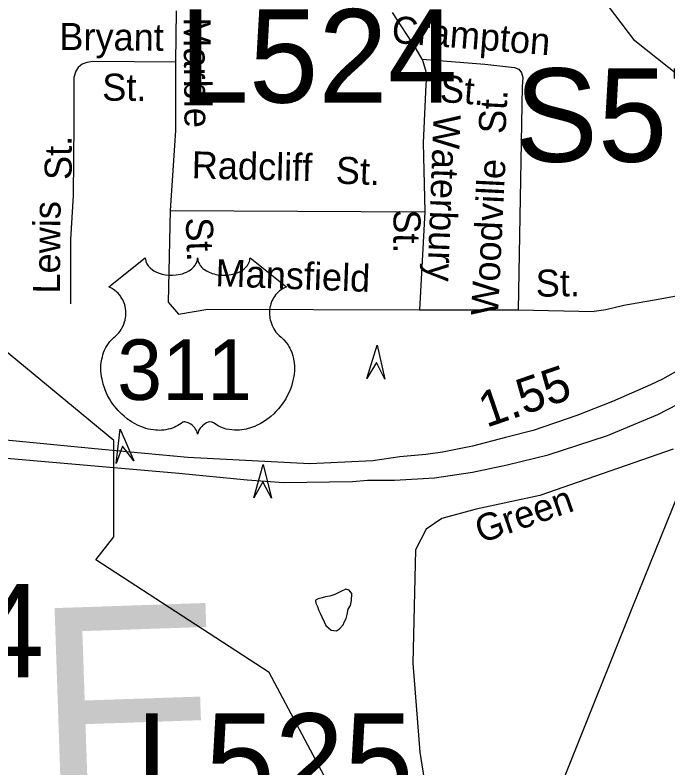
# Model space of a CAD drawing. Extents: x 1553981 to 1780076, y 812965 to 996873.
# Drawn here: x 1634902.9 to 1635189.7, y 846268.8 to 846599.4 of the extents above; entities that cross this region are included whole.
import ezdxf

# ---------------------------------------------------------------- set-up
doc = ezdxf.new("R2010")
doc.units = 0
for name, color, linetype in [('Exist Civil NCDOT Division Office Label', 7, 'Continuous'), ('Exist Civil NCDOT Garage or Maintenance Office CELL', 7, 'Continuous'), ('Exist Cultural Church with Cemetery CELL', 7, 'Continuous'), ('Exist Geographical Pit Clay CELL', 7, 'Continuous'), ('Exist Hydrographic Creek Single Shore', 7, 'Continuous'), ('Exist Hydrographic Misc Water Feature', 7, 'Continuous'), ('Exist Road Non-System Type 51 Label', 7, 'Continuous'), ('Exist Road Primary Interstate Divided Center Attributed', 7, 'Continuous'), ('Exist Road Primary Interstate Structure Cantilever Sign Number Label', 7, 'Continuous'), ('Exist Road Primary Interstate Structure Ovrhead Sign Number Label', 7, 'Continuous'), ('Exist Utilities Electrical Transmission Line', 7, 'Continuous'), ('Map Preparation Border County Name Lower Right Label', 7, 'Continuous')]:
    doc.layers.add(name, color=color, linetype=linetype)

msp = doc.modelspace()

# ---------------------------------------------------------------- linework, layer by layer
at = {"layer": 'Exist Cultural Church with Cemetery CELL'}
for points in [[(1635057.46, 846439.85), (1635061.92, 846454.42), (1635065.34, 846439.57), (1635061.65, 846446.81)], [(1634947.28, 846402.48), (1634948.96, 846417.63), (1634955.08, 846403.67), (1634950.11, 846410.09)], [(1635007.68, 846387.37), (1635011.85, 846402.03), (1635015.57, 846387.24), (1635011.73, 846394.41)]]:
    msp.add_lwpolyline(points, close=True, dxfattribs=at)
at = {"layer": 'Exist Geographical Pit Clay CELL'}
msp.add_lwpolyline([(1634960.06, 846492.83), (1634960.1, 846492.17), (1634960.27, 846491.38), (1634960.39, 846490.97), (1634960.76, 846490.19), (1634961.37, 846489.27), (1634962.22, 846488.37), (1634963.18, 846487.58), (1634963.82, 846487.16), (1634964.92, 846486.57), (1634966.16, 846486.05), (1634967.55, 846485.65), (1634968.96, 846485.37), (1634970.51, 846485.2), (1634972.04, 846485.17), (1634973.69, 846485.29), (1634975.51, 846485.64), (1634976.36, 846485.86), (1634977.3, 846486.18), (1634978.17, 846486.55), (1634979.13, 846487.06), (1634979.9, 846487.55), (1634980.5, 846487.99), (1634981.36, 846488.81), (1634982.03, 846489.65), (1634982.32, 846490.13), (1634982.57, 846490.58), (1634982.9, 846491.55), (1634983, 846491.98), (1634983.07, 846492.87), (1634983.12, 846492.12), (1634983.2, 846491.66), (1634983.32, 846491.2), (1634983.51, 846490.72), (1634983.85, 846490.03), (1634984.23, 846489.46), (1634984.95, 846488.62), (1634985.39, 846488.2), (1634985.8, 846487.87), (1634986.89, 846487.12), (1634988.17, 846486.47), (1634988.8, 846486.19), (1634989.44, 846485.97), (1634990.26, 846485.72), (1634991.1, 846485.52), (1634991.94, 846485.38), (1634992.79, 846485.25), (1634993.67, 846485.19), (1634994.38, 846485.17), (1634995.25, 846485.18), (1634996.06, 846485.23), (1634996.89, 846485.32), (1634997.8, 846485.47), (1634998.53, 846485.63), (1634999.5, 846485.89), (1635000.37, 846486.2), (1635001.14, 846486.54), (1635002.14, 846487.06), (1635002.94, 846487.56), (1635003.53, 846488.04), (1635004.23, 846488.68), (1635004.9, 846489.45), (1635005.29, 846490.01), (1635005.56, 846490.59), (1635005.82, 846491.2), (1635005.98, 846491.85), (1635006.05, 846492.41), (1635006.07, 846492.88), (1635022.14, 846480.08), (1635021.76, 846479.93), (1635020.89, 846479.51), (1635020.2, 846479.1), (1635019.09, 846478.32), (1635018.62, 846477.89), (1635018.14, 846477.45), (1635017.71, 846476.97), (1635017.32, 846476.52), (1635016.86, 846475.88), (1635016.44, 846475.23), (1635016.03, 846474.52), (1635015.73, 846473.9), (1635015.24, 846472.61), (1635015, 846471.79), (1635014.85, 846471.1), (1635014.66, 846469.67), (1635014.61, 846468.98), (1635014.61, 846468.31), (1635014.65, 846467.6), (1635014.72, 846466.91), (1635014.84, 846466.2), (1635014.95, 846465.57), (1635015.15, 846464.8), (1635015.44, 846463.91), (1635015.79, 846463.05), (1635016.52, 846461.65), (1635017.47, 846460.23), (1635018.14, 846459.43), (1635018.81, 846458.74), (1635019.8, 846457.91), (1635020.33, 846457.43), (1635020.95, 846456.82), (1635021.96, 846455.65), (1635022.37, 846455.1), (1635022.78, 846454.48), (1635023.16, 846453.84), (1635023.54, 846453.16), (1635023.84, 846452.56), (1635024.41, 846451.18), (1635024.82, 846449.84), (1635025.01, 846449.14), (1635025.31, 846447.56), (1635025.42, 846446.79), (1635025.55, 846445.25), (1635025.55, 846443.38), (1635025.41, 846441.62), (1635025.08, 846439.56), (1635024.8, 846438.32), (1635024.38, 846436.89), (1635023.97, 846435.64), (1635023.24, 846433.81), (1635022.59, 846432.48), (1635021.74, 846430.92), (1635021.16, 846429.98), (1635020.49, 846428.98), (1635019.64, 846427.82), (1635018.65, 846426.58), (1635017.47, 846425.28), (1635016.51, 846424.32), (1635015.26, 846423.2), (1635014.5, 846422.57), (1635013.41, 846421.76), (1635011.93, 846420.77), (1635010.47, 846419.92), (1635009.23, 846419.29), (1635008.13, 846418.81), (1635006.7, 846418.27), (1635004.33, 846417.62), (1635003.47, 846417.44), (1635002.44, 846417.28), (1635001.48, 846417.19), (1635000.55, 846417.13), (1634999.3, 846417.13), (1634998.05, 846417.23), (1634996.88, 846417.4), (1634995.65, 846417.65), (1634994.37, 846418.03), (1634993.21, 846418.49), (1634992.03, 846419.07), (1634990.04, 846420.32), (1634989.47, 846420.63), (1634989.14, 846420.71), (1634988.38, 846420.75), (1634987.65, 846420.6), (1634986.91, 846420.3), (1634986.47, 846420.07), (1634985.87, 846419.68), (1634985.42, 846419.32), (1634984.87, 846418.79), (1634984.49, 846418.36), (1634984.2, 846418.01), (1634983.64, 846417.13), (1634983.44, 846416.71), (1634983.23, 846416.17), (1634983.05, 846415.38), (1634982.79, 846416.38), (1634982.5, 846417.05), (1634982.16, 846417.62), (1634981.8, 846418.12), (1634981.24, 846418.77), (1634980.74, 846419.25), (1634980.13, 846419.74), (1634979.49, 846420.13), (1634978.97, 846420.4), (1634978.49, 846420.58), (1634977.91, 846420.72), (1634977.44, 846420.76), (1634977.05, 846420.75), (1634976.51, 846420.63), (1634975.79, 846420.1), (1634975.1, 846419.63), (1634974.35, 846419.16), (1634973.46, 846418.69), (1634972.8, 846418.38), (1634972.02, 846418.08), (1634971.11, 846417.78), (1634970.12, 846417.52), (1634969.11, 846417.32), (1634968.22, 846417.18), (1634967.26, 846417.09), (1634966.39, 846417.06), (1634965.49, 846417.07), (1634964.65, 846417.14), (1634963.67, 846417.23), (1634962.45, 846417.41), (1634961.45, 846417.63), (1634960.38, 846417.92), (1634959.29, 846418.26), (1634958.13, 846418.71), (1634956.66, 846419.34), (1634955.65, 846419.87), (1634954.04, 846420.79), (1634952.16, 846422.09), (1634950.74, 846423.24), (1634949.7, 846424.18), (1634948.18, 846425.74), (1634947.28, 846426.75), (1634945.87, 846428.58), (1634944.97, 846429.9), (1634944.38, 846430.87), (1634943.53, 846432.42), (1634943.06, 846433.4), (1634942.45, 846434.83), (1634941.97, 846436.13), (1634941.57, 846437.36), (1634941.36, 846438.15), (1634941.06, 846439.53), (1634940.87, 846440.51), (1634940.69, 846441.85), (1634940.59, 846443.26), (1634940.57, 846444.56), (1634940.61, 846445.65), (1634940.73, 846446.91), (1634940.94, 846448.25), (1634941.2, 846449.4), (1634941.43, 846450.22), (1634941.77, 846451.23), (1634942.22, 846452.34), (1634942.76, 846453.41), (1634943.26, 846454.29), (1634943.9, 846455.24), (1634944.53, 846456.05), (1634945.35, 846456.94), (1634946.2, 846457.76), (1634946.99, 846458.39), (1634947.92, 846459.3), (1634948.4, 846459.85), (1634948.98, 846460.62), (1634949.45, 846461.34), (1634949.82, 846461.97), (1634950.31, 846462.91), (1634950.6, 846463.62), (1634950.97, 846464.7), (1634951.16, 846465.46), (1634951.35, 846466.44), (1634951.47, 846467.36), (1634951.52, 846468.51), (1634951.49, 846469.46), (1634951.37, 846470.57), (1634951.16, 846471.63), (1634950.91, 846472.56), (1634950.51, 846473.63), (1634950.14, 846474.41), (1634949.52, 846475.46), (1634948.84, 846476.44), (1634948.13, 846477.24), (1634947.42, 846477.95), (1634946.74, 846478.48), (1634946.09, 846478.95), (1634945.27, 846479.44), (1634944.48, 846479.83), (1634943.99, 846480.03)], close=True, dxfattribs=at)
at = {"layer": 'Exist Hydrographic Creek Single Shore'}
msp.add_lwpolyline([(1635251.23, 845900.49), (1635241.98, 845905.61), (1635222.36, 845924.47), (1635148.73, 846037.17), (1635133.36, 846064.15), (1635107.11, 846126.24), (1635100.35, 846173.96), (1635092.23, 846190.95), (1635059.23, 846226.51), (1635014.48, 846310.71), (1634938.4, 846360.17), (1634946.3, 846370.23), (1634946.3, 846412.62), (1634889.57, 846459.33), (1634877.36, 846479.45), (1634841.23, 846557.55), (1634830.22, 846595.11), (1634817.1, 846624.51), (1634780.1, 846674.92), (1634763.85, 846710.53), (1634754.1, 846766.12)], dxfattribs=at)
at = {"layer": 'Exist Hydrographic Misc Water Feature'}
for points in [[(1635273.05, 846521.7), (1635246.36, 846531.67), (1635175.11, 846588.11), (1635148.36, 846623.53), (1635139.24, 846642.58), (1635138.35, 846652.87), (1635133.24, 846659.13), (1635132.24, 846667.76), (1635117.99, 846690.62), (1635082.73, 846711.85)], [(1635037.7, 846343.51), (1635035.99, 846343.07), (1635034.83, 846342.46), (1635034.99, 846341.14), (1635035.72, 846339.7), (1635036.17, 846338.3), (1635036.85, 846336.82), (1635037.63, 846335.15), (1635038.58, 846332.96), (1635039.42, 846331.36), (1635041.79, 846329.28), (1635044.07, 846328.98), (1635045.4, 846329.85), (1635047.02, 846331.61), (1635047.41, 846332.85), (1635048.36, 846334.5), (1635048.77, 846336.16), (1635049.19, 846338.6), (1635050.22, 846340.14), (1635050.63, 846342.38), (1635050.74, 846345.36), (1635049.68, 846346.88), (1635048.13, 846347.37), (1635046.26, 846346.42), (1635043.3, 846344.95), (1635041.16, 846344.32), (1635039.22, 846343.92), (1635037.7, 846343.51)]]:
    msp.add_lwpolyline(points, dxfattribs=at)
at = {"layer": 'Exist Road Primary Interstate Divided Center Attributed'}
for points in [[(1635310.9, 846514.99), (1635297.81, 846505.94), (1635206.93, 846450.34), (1635199, 846446.14), (1635187.26, 846439.53), (1635181.99, 846437), (1635165.26, 846429.66), (1635149.65, 846423.53), (1635130.45, 846416.93), (1635118.31, 846413.99), (1635103.77, 846410.13), (1635090.7, 846407.43), (1635083.37, 846406.49), (1635071.95, 846405.37), (1635060.1, 846403.72), (1635032.42, 846402.32), (1634978.81, 846405.12), (1634940.93, 846408.59), (1634838.36, 846418.57), (1634775.88, 846424.31)], [(1634847.02, 846409.33), (1634974.81, 846398.32), (1635004.81, 846395.26), (1635020.95, 846394.19), (1635051.03, 846394.59), (1635057.62, 846395.16), (1635069.56, 846395.12), (1635087.17, 846396.16), (1635103.77, 846398.66), (1635118.98, 846401.86), (1635136.98, 846406.26), (1635163.19, 846414.79), (1635185.2, 846424.03), (1635207.67, 846435.53), (1635224.87, 846445.4), (1635279.89, 846479.71), (1635322.1, 846505.59)]]:
    msp.add_lwpolyline(points, dxfattribs=at)
at = {"layer": 'Exist Utilities Electrical Transmission Line'}
msp.add_lwpolyline([(1634884.84, 845629.31), (1634920.94, 845715.84), (1634951.06, 845787.47), (1634981.74, 845861.81), (1635008.31, 845927.48), (1635051.4, 846035.19), (1635081.84, 846110.29), (1635115.63, 846194.12), (1635145.05, 846266.99), (1635174.19, 846339.64), (1635196.63, 846395.09), (1635225.27, 846466.72), (1635235.61, 846492.6), (1635246.94, 846559.2), (1635259.35, 846632.29), (1635266.9, 846675.21)], dxfattribs=at)
at = {"layer": 'Map Preparation Border County Name Lower Right Label'}
msp.add_line((1634973.67, 846601.25), (1634973.32, 846578.77), dxfattribs=at)
for points in [[(1635081.77, 846580.02), (1635079.09, 846584.57), (1635068.61, 846600.5)], [(1635081.77, 846580.02), (1635083.2, 846575.26), (1635083.64, 846572.25), (1635083.35, 846568.75), (1635082.18, 846543.26), (1635082.9, 846513.05)], [(1635081.77, 846580.02), (1635109.22, 846577.83), (1635122.2, 846576.37), (1635124.18, 846575.6), (1635125.4, 846574.08), (1635125.86, 846572.07), (1635125.56, 846568.07), (1635123.88, 846469.98)], [(1634973.32, 846578.77), (1634937.08, 846579.1), (1634934.32, 846578.63), (1634932.33, 846577.92), (1634930.55, 846576.46), (1634929.51, 846574.71), (1634928.73, 846571.97), (1634928.66, 846568.47), (1634928.65, 846551.99), (1634928.38, 846520.22), (1634927.16, 846500.93), (1634927.16, 846472.67)], [(1634973.32, 846578.77), (1634973.33, 846548.75), (1634970.98, 846513.61)], [(1634970.98, 846513.61), (1634970.06, 846473.36), (1634974.67, 846468.14), (1634987.56, 846470.29), (1635080.59, 846469.98)], [(1634970.98, 846513.61), (1635082.9, 846513.05)], [(1635082.9, 846513.05), (1635080.59, 846469.98)], [(1635207.2, 846478.38), (1635196.53, 846476.51), (1635186.26, 846474.64), (1635170.23, 846471.86), (1635162.39, 846469.98), (1635157.19, 846469.18)], [(1635080.59, 846469.98), (1635123.88, 846469.98)], [(1635123.88, 846469.98), (1635157.19, 846469.18)], [(1635191.92, 846408.84), (1635133.33, 846388.45), (1635105.44, 846382.5), (1635090.4, 846378.42), (1635083.51, 846373.72), (1635078.81, 846364.62), (1635077.56, 846314.77), (1635080.7, 846275.75), (1635087.6, 846232.17)]]:
    msp.add_lwpolyline(points, dxfattribs=at)

# ---------------------------------------------------------------- texts
at = {"layer": 'Exist Civil NCDOT Division Office Label'}
msp.add_text('1.55', height=15.625, rotation=18.9704, dxfattribs=at).set_placement((1635109.91, 846418.13))
at = {"layer": 'Exist Civil NCDOT Garage or Maintenance Office CELL'}
msp.add_text('311', height=26.562, dxfattribs=at).set_placement((1634947.71, 846430.42))
at = {"layer": 'Exist Road Non-System Type 51 Label'}
for s, height, rotation, p in [('Marble', 11.875, 270.5413, (1634976.86, 846598.35)), ('Crampton', 11.875, 355.4514, (1635068, 846587.28)), ('Bryant', 11.875, 359.469, (1634922.27, 846584.11)), ('St.', 11.875, 359.469, (1634941.1, 846561.86)), ('St.', 11.875, 355.4514, (1635089.25, 846561.34)), ('St.', 11.875, 86.8517, (1635118.24, 846547.04)), ('Waterbury', 11.875, 267.8396, (1635086.76, 846555.86)), ('St.', 11.875, 89.9658, (1634927.74, 846526.99)), ('Radcliff', 11.875, 358.6947, (1634980.36, 846527.72)), ('St.', 11.875, 357.8046, (1635043.58, 846525.44)), ('Woodville', 11.875, 87.2056, (1635115.01, 846467.21)), ('Lewis', 11.875, 89.5132, (1634922.54, 846477.08)), ('St.', 11.875, 269.6, (1635069.16, 846514.16)), ('St.', 11.875, 271.8344, (1634977.84, 846510.43)), ('Mansfield', 11.875, 357.8385, (1634990.75, 846480.39)), ('St.', 11.875, 0.848, (1635131.66, 846475.71)), ('Green', 11.875, 19.2504, (1635107.48, 846367.35)), ('E.', 95, 1.9459, (1634913.03, 846243.7))]:
    msp.add_text(s, height=height, rotation=rotation, dxfattribs=at).set_placement(p)
at = {"layer": 'Exist Road Primary Interstate Structure Cantilever Sign Number Label'}
for s, p in [('L524', (1634975.08, 846560.99)), ('L534', (1634793.66, 846308.63)), ('L525', (1634955.88, 846251.74))]:
    msp.add_text(s, height=41.01, dxfattribs=at).set_placement(p)
at = {"layer": 'Exist Road Primary Interstate Structure Ovrhead Sign Number Label'}
msp.add_text('S575', height=41.01, dxfattribs=at).set_placement((1635122.32, 846535))

doc.saveas('drawing.dxf')
